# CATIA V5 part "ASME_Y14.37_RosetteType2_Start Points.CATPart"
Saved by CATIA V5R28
Part number: 333X3333-303
Revision: --
Nomenclature: ASME_Y14.37_RosetteType2
Bounding box of the stored display mesh (mm): x -188.298 to 149.059, y -714.612 to 664.697, z 0 to 91.639
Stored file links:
  C:\Users\jvl2147\Documents\AP242 testing\Composite Example Parts for PER\Start Points - CWB\ASME_Y14.37_RosetteType2_Start Points.CATPart
  \\NW\Data\MSE-Composites\ASME Y14.37\ASME Y-14.37_COMPOSITES.CATMaterial
  C:\Users\jvl2147\AppData\Local\DassaultSystemes\CATTemp\B28SP3PRALL\333X3333-303_Ply Group - 333X3333-303_StaggerOrigin.txt
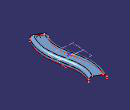
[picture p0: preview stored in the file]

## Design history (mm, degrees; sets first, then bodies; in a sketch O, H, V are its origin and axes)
AxisSystem1 "ROSETTE COORDINATE SYSTEM": origin (-72.9205, -637.9645, 93.98), X (0.5026, 0.8645, 0), Y (-0.8645, 0.5026, 0), Z (0, 0, 1)
CompParametersFeature1 "CATCoParametersFeatName": Value 0, Value 45, Value -45, Value 90
CompEOPGroupFeature1 "CATCoEOPGroupFeatName"
CompStacking1 "Stacking"
CompIsoThickAreasGroup1 "CATCoIsoThickAreasGroupFeatName": RefAddThickness 0
TTRSSet1
f4a2d38f3ddc11d3a929006094b99c4b_11 "CATTPSSet"
CompReviewTools1 "Review tools"
Set1 "CONSTRUCTION GEOMETRY"
  Set2 "CONSTRUCTION - LAMINATE REFERENCE SURFACE"
    Sketch1 on xy-plane, origin (0, 0, 0), H (1, 0, 0), V (0, 1, 0)
      spline S1 through (-79.505, -649.09) (21.2912, -260.3998) (-51.6257, 228.8061) (37.963, 602.845)
    Plane1: type Normal, Curve Sketch1, RefPoint vertex of Sketch1, Ratio 0
    Sketch2 on Plane1, origin (-464.3095, -417.3341, 0), H (-0.8566, 0.5159, 0), V (0, 0, 1)
      line L1 (-525.4052, 91.6386) -> (-373.0052, 91.6386)
      line L2 (-322.2052, 40.8386) -> (-322.2052, 0)
      line L3 (-576.2052, 0) -> (-576.2052, 40.8386)
      reference projected point E1 (-449.2052, 0) from vertex of Sketch1
      reference projected point E2 (-449.2052, 0) from vertex of Sketch1
      arc A1 centre (-373.0052, 40.8386) radius 50.8 from (-373.0052, 91.6386) to (-322.2052, 40.8386) cw
      arc A2 centre (-525.4052, 40.8386) radius 50.8 from (-576.2052, 40.8386) to (-525.4052, 91.6386) cw
      distance E1 L2 = 127
      distance E2 L3 = 127
      radius A1 = 50.8
      radius A2 = 50.8
      horizontal: L1 H
      vertical: L2 V, L3 V
      tangency: A1 L1, A1 L2, A2 L3, A2 L1
    Sweep1: type Unspec, Profile Sketch2, Guide Sketch1
  Set3 "CONSTRUCTION - PLIES EOPS"
    Plane2: type Normal, Curve Sketch1, RefPoint vertex of Sketch1, Ratio 0
    Plane3: type Normal, Curve Sketch1, RefPoint {point type OnCurve, Support Sketch1, Length 1118.262}, Ratio 0.99
    Plane4: type Normal, Curve Sketch1, Ratio 0.01
    Intersect1: ToIntersect1 Plane3, ToIntersect2 Sweep1
    Intersect2: ToIntersect1 Sweep1, ToIntersect2 Plane4
    Plane5: type Offset, RefPlane xy-plane, Offset 2.54
    Intersect3: ToIntersect1 Plane5, ToIntersect2 Join1
    Near1: MultiElement Intersect3, ReferenceElement edge of Sweep1
    Near2: MultiElement Intersect3, ReferenceElement edge of Sweep1
  Set4 "CONSTRUCTION - ROSETTE COORDINATE SYSTEM"
    Intersect4: ToIntersect1 Plane4, ToIntersect2 Project2
    Line1: type Tangency, RefPoint Intersect4, Curve Project2, Start 0, End 25.4
    Plane6: type Offset, RefPlane xy-plane, Offset 93.98
    Project1 "PROJECT": ToProject Sketch1, Support Join1, Direction xy-plane
  Set5 "CONSTRUCTION - ROSETTE TRANSFORMS"
    Line2 "Ply.1_Rosette_transfer_X": type Tangency, RefPoint {point type OnCurve, Support Project2, Length 288.56}, Curve Project2, Support Join1, Start 0, End 25.4
    Line3 "Ply.1_Rosette_transfer_X.Renamed": type Tangency, RefPoint {point type OnCurve, Support Project2, Length 536.186}, Curve Project2, Support Join1, Start 25.4, End 0
    Line4 "Ply.1_Rosette_transfer_X.Renamed": type Tangency, RefPoint {point type OnCurve, Support Project2, Length 783.62}, Curve Project2, Support Join1, Start 25.4, End 0
    Line5 "Ply.1_Rosette_transfer_X.Renamed": type Tangency, RefPoint {point type OnCurve, Support Project2, Length 1274.71}, Curve Project2, Support Join1, Start 25.4, End 0
    Line6 "Ply.1_Rosette_transfer_X.Renamed": type Tangency, RefPoint {point type OnCurve, Support Project2, Length 1017.245}, Curve Project2, Support Join1, Start 25.4, End 0
    AxisSystem2 "ROSETTE COORDINATE SYSTEM": origin (16.8931, -379.3831, 93.98), X (0.1242, 0.9923, 0), Y (-0.9923, 0.1242, 0), Z (0, 0, 1)
    AxisSystem3 "ROSETTE COORDINATE SYSTEM.Renamed": origin (7.1166, -132.8437, 93.98), X (-0.1632, 0.9866, 0), Y (-0.9866, -0.1632, 0), Z (0, 0, 1)
    AxisSystem4 "ROSETTE COORDINATE SYSTEM.Renamed1": origin (-38.9217, 110.2518, 93.98), X (-0.1571, 0.9876, 0), Y (-0.9876, -0.1571, 0), Z (0, 0, 1)
    AxisSystem5 "ROSETTE COORDINATE SYSTEM.Renamed2": origin (29.3229, 586.9432, 93.98), X (0.4677, 0.8839, 0), Y (-0.8839, 0.4677, 0), Z (0, 0, 1)
    AxisSystem6 "ROSETTE COORDINATE SYSTEM.Renamed3": origin (-47.995, 342.9553, 93.98), X (0.1137, 0.9935, 0), Y (-0.9935, 0.1137, 0), Z (0, 0, 1)
    Point1: type OnSurface, Support Join1, Length 362.156, Direction (-0.4364, -0.3881, 0.8118)
    Line7: type Normal, RefPoint Point1, RefSkin Join1, Start 254, End 0
  Plane7: type Offset, RefPlane YZ plane of AxisSystem2, Offset 0
  Circle1: type CtrRad, Start 0, End 180, Center {point type OnSurface, Support Join1, Length 336.531, Direction (0.5738, 0.5102, 0.6407)}, Support Join1, Radius 50.8, FirstDirection (1, 0, 0)
  CurvePar1: Offset Near1, Support Join1, Offset2 0, Offset1 50.8
Set6 "ENGINEERING GEOMETRY"
  Set7 "LAMINATE REFERENCE SURFACE"
    Join1 "LAMINATE REFERENCE SURFACE": Elements Sweep1
  Set8 "GUIDE CURVE - ZERO DEGREE ORIENTATION"
    Project2 "GUIDE CURVE - 0°": ToProject Sketch1, Support Plane6
Body1 (main body)
Body2 "-303"
  CompIsoThickAreasSolid1 "Area Solid.1": IsoAreasGroup CompIsoThickAreasGroup1
Set9 "MANUFACTURING"
  Point2 "StartingPoint_Ply P2": stored without definition
Set10 "MANUFACTURING"
  Point3 "StartingPoint_Ply P3": stored without definition
Set11 "MANUFACTURING"
  Point4 "StartingPoint_Ply P5": stored without definition
Set12 "MANUFACTURING"
  Point5 "StartingPoint_Ply P6": stored without definition
Set13 "MANUFACTURING"
  Point6 "StartingPoint_Ply P8": stored without definition
Set14 "MANUFACTURING"
  Point7 "StartingPoint_Ply P4": stored without definition
Set15 "MANUFACTURING"
  Point8 "StartingPoint_Ply P7": stored without definition
Set16 "MANUFACTURING"
  Point9 "StartingPoint_Ply P9": stored without definition
Set17 "MANUFACTURING"
  Point10 "StartingPoint_Ply P1": stored without definition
